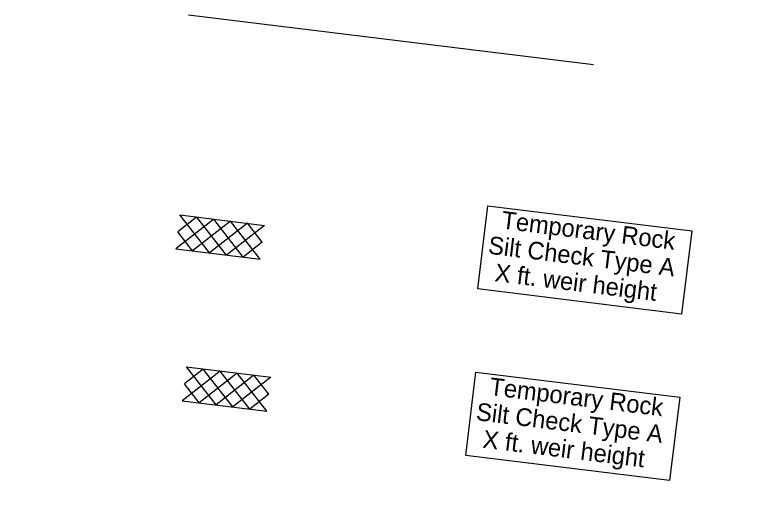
# Model space of a CAD drawing. Extents: x 2470000 to 2520000, y 340000 to 380000.
# Drawn here: x 2482786.9 to 2483038.1, y 374300.7 to 374470.5 of the extents above; entities that cross this region are included whole.
import ezdxf

# ---------------------------------------------------------------- set-up
doc = ezdxf.new("R2010")
doc.units = 0
for name, color, linetype in [('Exist Roads Hard Surface Topo Text', 7, 'Continuous'), ('Rock Silt Check Type A Both CELL', 7, 'Continuous'), ('Rock Silt Check Type A CG CELL', 7, 'Continuous'), ('Rock Silt Check Type A Note Both CELL', 7, 'Continuous'), ('Rock Silt Check Type A Note CG CELL', 7, 'Continuous'), ('Scratch_Level_6', 7, 'Continuous')]:
    doc.layers.add(name, color=color, linetype=linetype)

msp = doc.modelspace()

# ---------------------------------------------------------------- linework, layer by layer
at = {"layer": 'Exist Roads Hard Surface Topo Text'}
msp.add_line((2482845.97, 374470.48), (2482983.52, 374453.57), dxfattribs=at)
at = {"layer": 'Rock Silt Check Type A Both CELL'}
for p, q in [((2482850.87, 374350.24), (2482844.51, 374345.28)), ((2482845.22, 374350.99), (2482873.9, 374347.46)), ((2482855.27, 374338.11), (2482845.22, 374350.99)), ((2482861.03, 374337.41), (2482850.93, 374350.28)), ((2482856.68, 374349.58), (2482843.81, 374339.52)), ((2482862.44, 374348.87), (2482849.52, 374338.82)), ((2482868.15, 374348.18), (2482855.27, 374338.11)), ((2482866.74, 374336.7), (2482856.68, 374349.58)), ((2482872.49, 374336), (2482862.44, 374348.87)), ((2482873.21, 374341.75), (2482868.15, 374348.18)), ((2482849.52, 374338.82), (2482844.51, 374345.28)), ((2482873.9, 374347.46), (2482861.03, 374337.41)), ((2482873.21, 374341.75), (2482866.74, 374336.7)), ((2482843.81, 374339.52), (2482872.49, 374336))]:
    msp.add_line(p, q, dxfattribs=at)
at = {"layer": 'Rock Silt Check Type A CG CELL'}
for p, q in [((2482854.47, 374401.14), (2482841.6, 374391.08)), ((2482848.66, 374401.8), (2482842.3, 374396.84)), ((2482843.01, 374402.55), (2482871.69, 374399.02)), ((2482853.06, 374389.68), (2482843.01, 374402.55)), ((2482860.23, 374400.43), (2482847.31, 374390.38)), ((2482858.82, 374388.97), (2482848.72, 374401.85)), ((2482864.53, 374388.27), (2482854.47, 374401.14)), ((2482870.28, 374387.56), (2482860.23, 374400.43)), ((2482865.94, 374399.74), (2482853.06, 374389.68)), ((2482871.69, 374399.02), (2482858.82, 374388.97)), ((2482871, 374393.31), (2482865.94, 374399.74)), ((2482847.31, 374390.38), (2482842.3, 374396.84)), ((2482871, 374393.31), (2482864.53, 374388.27)), ((2482841.6, 374391.08), (2482870.28, 374387.56))]:
    msp.add_line(p, q, dxfattribs=at)
at = {"layer": 'Rock Silt Check Type A Note Both CELL'}
msp.add_lwpolyline([(2482943.55, 374349.23), (2483012.81, 374340.71), (2483009.33, 374312.46), (2482940.08, 374320.97)], close=True, dxfattribs=at)
at = {"layer": 'Rock Silt Check Type A Note CG CELL'}
msp.add_lwpolyline([(2482947.64, 374405.71), (2483016.9, 374397.2), (2483013.43, 374368.95), (2482944.17, 374377.46)], close=True, dxfattribs=at)

# ---------------------------------------------------------------- texts
at = {"layer": 'Rock Silt Check Type A Note Both CELL'}
for s, p in [('Temporary Rock', (2482947.92, 374341.48)), ('Silt Check Type A', (2482943.39, 374332.96)), ('X ft. weir height', (2482945.63, 374323.62))]:
    msp.add_text(s, height=6, rotation=352.9921, dxfattribs=at).set_placement(p)
at = {"layer": 'Rock Silt Check Type A Note CG CELL'}
for s, p in [('Temporary Rock', (2482952.02, 374397.96)), ('Silt Check Type A', (2482947.49, 374389.45)), ('X ft. weir height', (2482949.73, 374380.11))]:
    msp.add_text(s, height=6, rotation=352.9921, dxfattribs=at).set_placement(p)
at = {"layer": 'Scratch_Level_6'}
msp.add_text('4387', height=1000, dxfattribs=at).set_placement((2482689.75, 373444.66))

doc.saveas('drawing.dxf')
